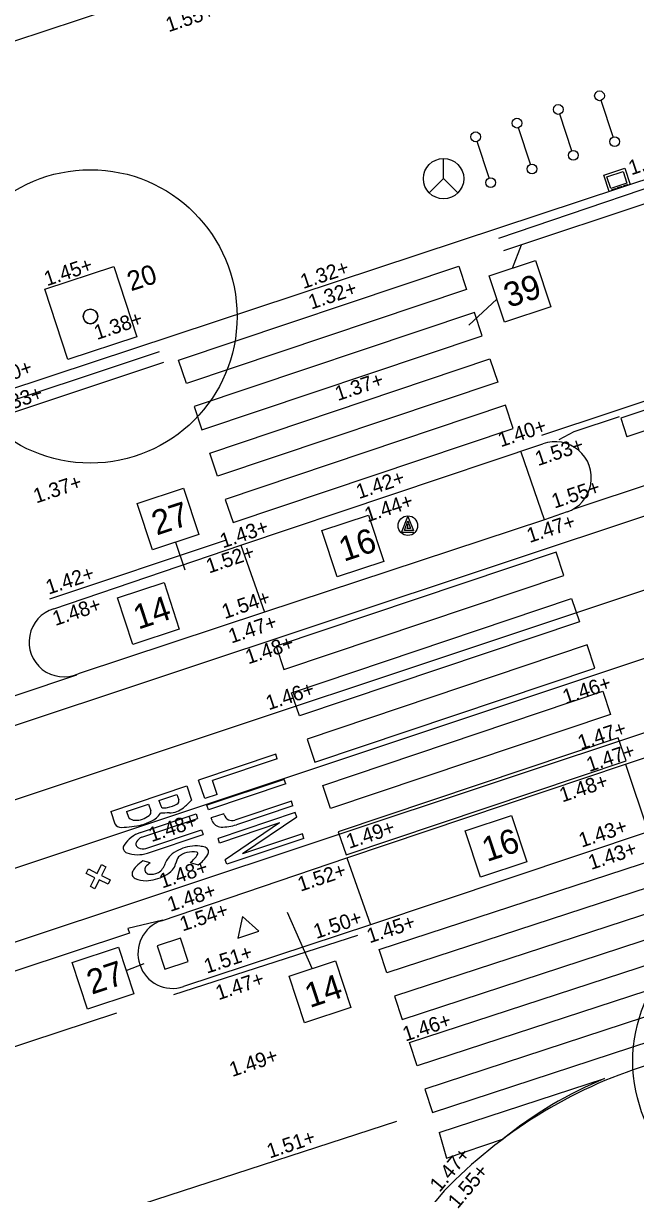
# Model space of a CAD drawing. Extents: x 122462 to 123306, y 485548 to 486417.
# Drawn here: x 122817.52 to 122830.05, y 486173.11 to 486197.04 of the extents above; entities that cross this region are included whole.
import ezdxf

# ---------------------------------------------------------------- set-up
doc = ezdxf.new("R2010")
doc.units = 0
for name, color, linetype in [('B meubilair trammast', 7, 'Continuous'), ('B-WE-GR-BOOM_BOOMDIAMETER', 7, 'Continuous'), ('B-WE-OG-HOOGTEPUNT-S', 7, 'Continuous'), ('B-WE-OG-TOPOKAART-G', 7, 'Continuous'), ('iba7-verkeersbord rood', 7, 'Continuous'), ('V markering 1-1 10 cm', 7, 'Continuous'), ('V markering figuratie', 7, 'Continuous'), ('V markering haaientanden', 7, 'Continuous'), ('V markering ononderbroken streep 10 cm', 7, 'Continuous'), ('V materiaalscheiding algemeen', 7, 'Continuous'), ('V meubilair ANWB paal', 7, 'Continuous'), ('V meubilair fietsenrek', 7, 'Continuous'), ('V meubilair verkeersbord', 7, 'Continuous'), ('V opsluitband 100x200 mm', 7, 'Continuous'), ('V Rails', 7, 'Continuous'), ('V riool trottoirkolk', 7, 'Continuous'), ('V Scheidingsband tramband', 7, 'Continuous'), ('V trottoirband 180-200x250 mm specie', 7, 'Continuous'), ('X-WE-AL-TEKENBLAD-S', 7, 'Continuous')]:
    doc.layers.add(name, color=color, linetype=linetype)

msp = doc.modelspace()

# ---------------------------------------------------------------- linework, layer by layer
at = {"layer": 'B meubilair trammast'}
msp.add_lwpolyline([(122821.912, 486178.335), (122822.339, 486178.475), (122822.004, 486178.776)], close=True, dxfattribs=at)
at = {"layer": 'B-WE-OG-TOPOKAART-G'}
msp.add_lwpolyline([(122815.999, 486196.239), (122819.975, 486197.551), (122824.066, 486198.901)], dxfattribs=at)
at = {"layer": 'iba7-verkeersbord rood'}
for centre, radius in [((122818.894, 486191.046), 3), ((122818.894, 486191.046), 0.15), ((122832.992, 486175.817), 3)]:
    msp.add_circle(centre, radius, dxfattribs=at)
for start, end in [(0, 180), (180, 0)]:
    msp.add_arc((122818.894, 486191.046), 0.15, start, end, dxfattribs=at)
at = {"layer": 'V markering 1-1 10 cm'}
for points in [[(122854.874, 486201.561), (122851.93, 486200.584), (122836.82, 486195.535), (122827.344, 486192.387)], [(122827.25, 486192.644), (122831.993, 486194.256)], [(122820.303, 486190.322), (122804.286, 486185), (122793.007, 486181.252)], [(122820.386, 486190.104), (122804.368, 486184.77), (122793.094, 486180.995)], [(122814.686, 486175.249), (122819.433, 486176.807)]]:
    msp.add_lwpolyline(points, dxfattribs=at)
at = {"layer": 'V markering figuratie'}
for p, q in [((122712.845, 486143.511), (122860.885, 486192.728)), ((122822.687, 486182.094), (122821.107, 486181.565)), ((122822.718, 486182), (122821.394, 486181.557)), ((122822.718, 486182), (122822.687, 486182.094)), ((122821.233, 486181.188), (122821.107, 486181.565)), ((122822.858, 486181.581), (122821.278, 486181.052)), ((122822.89, 486181.487), (122821.31, 486180.958)), ((122821.488, 486181.274), (122821.394, 486181.557)), ((122822.89, 486181.487), (122822.858, 486181.581)), ((122819.31, 486180.926), (122820.865, 486181.446)), ((122820.296, 486181.149), (122820.665, 486181.271)), ((122820.665, 486181.271), (122820.701, 486181.163)), ((122820.865, 486181.446), (122820.963, 486181.155)), ((122821.488, 486181.274), (122821.233, 486181.188)), ((122819.634, 486180.927), (122820.081, 486181.077)), ((122820.081, 486181.077), (122820.128, 486180.94)), ((122820.296, 486181.149), (122820.333, 486181.037)), ((122821.31, 486180.958), (122821.278, 486181.052)), ((122823.008, 486181.134), (122821.851, 486180.747)), ((122823.039, 486181.041), (122821.882, 486180.653)), ((122823.039, 486181.041), (122823.008, 486181.134)), ((122819.31, 486180.926), (122819.395, 486180.672)), ((122819.634, 486180.927), (122819.675, 486180.805)), ((122819.917, 486180.496), (122821.055, 486180.877)), ((122819.948, 486180.402), (122821.086, 486180.783)), ((122821.055, 486180.877), (122821.086, 486180.783)), ((122821.621, 486180.879), (122821.365, 486180.793)), ((122821.382, 486180.743), (122821.365, 486180.793)), ((122823.086, 486180.902), (122821.506, 486180.373)), ((122821.628, 486180.858), (122821.621, 486180.879)), ((122823.116, 486180.81), (122822.009, 486180.059)), ((122823.116, 486180.81), (122823.086, 486180.902)), ((122820.029, 486180.166), (122821.167, 486180.546)), ((122821.167, 486180.546), (122821.198, 486180.452)), ((122822.762, 486180.689), (122821.537, 486180.279)), ((122822.762, 486180.689), (122821.652, 486179.936)), ((122820.06, 486180.071), (122821.198, 486180.452)), ((122821.537, 486180.279), (122821.506, 486180.373)), ((122823.262, 486180.374), (122821.682, 486179.845)), ((122823.231, 486180.468), (122822.009, 486180.059)), ((122823.262, 486180.374), (122823.231, 486180.468)), ((122820.115, 486179.874), (122819.967, 486179.917)), ((122820.935, 486179.881), (122821.097, 486179.831)), ((122821.682, 486179.845), (122821.652, 486179.936))]:
    msp.add_line(p, q, dxfattribs=at)
for points in [[(122826.592, 486191.599), (122820.858, 486189.675), (122820.699, 486190.149), (122826.433, 486192.073)], [(122821.176, 486188.727), (122826.91, 486190.651), (122826.751, 486191.125), (122821.017, 486189.201)], [(122827.228, 486189.703), (122821.494, 486187.779), (122821.335, 486188.253), (122827.069, 486190.177)], [(122821.812, 486186.831), (122827.546, 486188.755), (122827.387, 486189.229), (122821.653, 486187.305)], [(122822.852, 486183.827), (122828.581, 486185.751), (122828.422, 486186.225), (122822.693, 486184.301)], [(122828.9, 486184.803), (122823.171, 486182.879), (122823.011, 486183.353), (122828.74, 486185.277)], [(122823.489, 486181.931), (122829.218, 486183.855), (122829.059, 486184.329), (122823.33, 486182.405)], [(122829.536, 486182.907), (122823.807, 486180.983), (122823.648, 486181.457), (122829.377, 486183.381)], [(122824.126, 486180.035), (122829.855, 486181.959), (122829.695, 486182.433), (122823.966, 486180.509)], [(122819.12, 486179.838), (122819.21, 486179.793), (122819.12, 486179.614), (122819.299, 486179.525), (122819.254, 486179.435), (122819.075, 486179.525), (122818.986, 486179.346), (122818.896, 486179.391), (122818.986, 486179.57), (122818.807, 486179.659), (122818.852, 486179.749), (122819.031, 486179.659)], [(122830.662, 486179.487), (122824.96, 486177.624), (122824.805, 486178.099), (122830.507, 486179.963)], [(122825.271, 486176.673), (122830.973, 486178.537), (122830.817, 486179.012), (122825.115, 486177.148)], [(122831.283, 486177.586), (122825.581, 486175.723), (122825.426, 486176.198), (122831.128, 486178.062)], [(122825.892, 486174.772), (122831.594, 486176.636), (122831.439, 486177.111), (122825.737, 486175.247)]]:
    msp.add_lwpolyline(points, close=True, dxfattribs=at)
for points in [[(122826.029, 486174.358), (122829.417, 486175.462)], [(122826.029, 486174.358), (122826.18, 486173.836), (122827.344, 486174.231)]]:
    msp.add_lwpolyline(points, dxfattribs=at)
for centre, radius, start, end in [((122820.398, 486181.057), 0.0675, 197.2524, 243.0662), ((122820.379, 486181.473), 0.476, 268.5689, 281.1936), ((122820.333, 486181.687), 0.695, 281.465, 298.5477), ((122820.49, 486181.387), 0.493, 272.2905, 308.6433), ((122820.635, 486181.14), 0.0697, 295.5776, 19.8117), ((122819.955, 486182.077), 1.366, 308.078, 317.5423), ((122819.699, 486180.814), 0.0256, 198.7735, 228.6878), ((122819.813, 486180.944), 0.199, 228.6878, 267.2153), ((122819.823, 486181.193), 0.448, 267.4989, 287.6099), ((122819.782, 486181.244), 0.51, 290.3181, 307.9776), ((122820.047, 486180.912), 0.0849, 304.6771, 18.905), ((122819.968, 486181.119), 0.428, 292.9181, 327.2918), ((122820.499, 486178.524), 2.37, 89.7455, 94.1316), ((122821.795, 486180.914), 0.176, 198.5084, 288.5084), ((122819.512, 486180.728), 0.13, 205.5478, 277.0875), ((122819.457, 486182.885), 2.287, 271.7957, 277.0839), ((122819.56, 486182.233), 1.628, 276.2971, 283.5646), ((122819.625, 486181.756), 1.15, 286.003, 296.2854), ((122821.572, 486180.807), 0.201, 198.5084, 268.4664), ((122821.591, 486181.522), 0.916, 268.4678, 288.5084), ((122820.158, 486179.841), 0.698, 110.1773, 145.4219), ((122819.905, 486180.256), 0.0816, 146.7834, 250.5599), ((122820.04, 486180.188), 0.233, 113.1225, 150.9839), ((122819.675, 486180.179), 0.109, 147.4911, 249.9891), ((122819.86, 486180.739), 0.698, 251.4584, 286.7029), ((122819.974, 486180.392), 0.233, 245.6159, 283.4773), ((122820.815, 486179.724), 0.413, 126.6151, 160.1416), ((122820.997, 486179.512), 0.692, 111.671, 128.1579), ((122820.925, 486179.762), 0.327, 99.9568, 134.4098), ((122821.099, 486179.242), 0.981, 99.9642, 111.426), ((122820.986, 486179.563), 0.534, 80.7646, 102.7272), ((122821.048, 486179.648), 0.573, 81.5189, 101.9729), ((122820.528, 486180.406), 0.666, 307.8236, 327.0926), ((122821.061, 486180.062), 0.0305, 326.6033, 70.3406), ((122821.071, 486179.637), 0.581, 72.5811, 83.8728), ((122821.213, 486180.098), 0.0987, 325.9572, 71.0302), ((122820.447, 486179.225), 0.842, 124.7705, 136.9964), ((122820.305, 486179.565), 0.362, 121.5479, 141.3153), ((122820.079, 486179.975), 0.365, 304.3033, 342.4534), ((122820.325, 486179.93), 0.322, 321.1525, 345.9772), ((122820.983, 486179.795), 0.35, 145.0731, 170.6952), ((122820.715, 486180.391), 0.678, 304.3623, 315.9404), ((122820.611, 486180.459), 0.8, 317.5739, 328.6429), ((122819.845, 486179.649), 0.101, 147.3653, 249.6796), ((122820.099, 486179.524), 0.384, 134.125, 151.991), ((122820.102, 486179.739), 0.0964, 146.7417, 255.9783), ((122820.142, 486179.946), 0.307, 258.1175, 297.6026), ((122819.964, 486180.477), 0.974, 285.6661, 297.1748), ((122820.123, 486180.196), 0.651, 296.0499, 314.0333), ((122820.043, 486180.102), 0.595, 246.9456, 268.9442), ((122819.992, 486180.352), 0.846, 272.7296, 286.1609), ((122832.526, 486167.865), 8.209, 112.2586, 129.1472)]:
    msp.add_arc(centre, radius, start, end, dxfattribs=at)
at = {"layer": 'V markering haaientanden'}
msp.add_lwpolyline([(122815.839, 486171.566), (122825.165, 486174.59)], dxfattribs=at)
at = {"layer": 'V markering ononderbroken streep 10 cm'}
for points in [[(122828.129, 486188.619), (122841.373, 486193.005), (122851.321, 486196.3)], [(122818.06, 486185.269), (122821.656, 486186.469)], [(122820.6, 486177.184), (122824.365, 486178.394)]]:
    msp.add_lwpolyline(points, dxfattribs=at)
at = {"layer": 'V materiaalscheiding algemeen'}
for points in [[(122828.771, 486187.102), (122837.36, 486189.952), (122848.716, 486193.729), (122856.341, 486196.233), (122866.652, 486199.655), (122878.268, 486203.536), (122881.909, 486204.772)], [(122828.488, 486188.532), (122828.792, 486188.691), (122829.724, 486188.997)], [(122802.962, 486178.476), (122818.617, 486183.717)], [(122820.373, 486178.699), (122819.656, 486178.534), (122819.692, 486178.438), (122804.62, 486173.448), (122804.792, 486172.968)]]:
    msp.add_lwpolyline(points, dxfattribs=at)
at = {"layer": 'V meubilair ANWB paal'}
for q in [(122826.121, 486194.276), (122825.829, 486193.571), (122826.413, 486193.571)]:
    msp.add_line((122826.121, 486193.863), q, dxfattribs=at)
msp.add_circle((122826.121, 486193.863), 0.413, dxfattribs=at)
at = {"layer": 'V meubilair fietsenrek'}
for p, q in [((122829.591, 486194.715), (122829.344, 486195.462)), ((122828.745, 486194.435), (122828.498, 486195.182)), ((122827.9, 486194.156), (122827.653, 486194.903)), ((122827.054, 486193.877), (122826.808, 486194.623))]:
    msp.add_line(p, q, dxfattribs=at)
for centre in [(122829.312, 486195.557), (122828.467, 486195.277), (122827.622, 486194.998), (122826.776, 486194.718), (122829.622, 486194.62), (122828.777, 486194.341), (122827.931, 486194.061), (122827.086, 486193.782)]:
    msp.add_circle(centre, 0.1, dxfattribs=at)
at = {"layer": 'V meubilair verkeersbord'}
msp.add_lwpolyline([(122825.515, 486186.63), (122825.263, 486186.63), (122825.39, 486186.953), (122825.504, 486186.668), (122825.319, 486186.668), (122825.39, 486186.868), (122825.446, 486186.708), (122825.377, 486186.708), (122825.39, 486186.748), (122825.391, 486186.798)], dxfattribs=at)
msp.add_lwpolyline([(122820.418, 486177.702), (122820.893, 486177.859), (122820.736, 486178.333), (122820.261, 486178.177)], close=True, dxfattribs=at)
msp.add_circle((122825.39, 486186.768), 0.2, dxfattribs=at)
at = {"layer": 'V opsluitband 100x200 mm'}
msp.add_lwpolyline([(122819.846, 486190.627), (122818.434, 486190.163), (122817.962, 486191.602), (122819.374, 486192.066)], close=True, dxfattribs=at)
at = {"layer": 'V Rails'}
for p, q in [((122714.919, 486148.627), (122859.557, 486196.72)), ((122715.373, 486147.26), (122860.011, 486195.354)), ((122712.39, 486144.878), (122860.43, 486194.095))]:
    msp.add_line(p, q, dxfattribs=at)
at = {"layer": 'V riool trottoirkolk'}
for p, q in [((122829.4, 486193.932), (122829.827, 486194.074)), ((122829.51, 486193.6), (122829.4, 486193.932)), ((122829.827, 486194.074), (122829.937, 486193.741)), ((122829.937, 486193.741), (122829.51, 486193.6)), ((122829.757, 486193.697), (122829.681, 486193.672)), ((122829.771, 486193.686), (122829.77, 486193.691)), ((122829.795, 486193.694), (122829.793, 486193.699)), ((122829.831, 486193.722), (122829.8, 486193.712)), ((122829.876, 486193.737), (122829.831, 486193.722)), ((122829.89, 486193.726), (122829.888, 486193.73)), ((122829.557, 486193.616), (122829.556, 486193.62)), ((122829.638, 486193.658), (122829.562, 486193.633)), ((122829.652, 486193.647), (122829.651, 486193.652)), ((122829.676, 486193.655), (122829.675, 486193.66))]:
    msp.add_line(p, q, dxfattribs=at)
msp.add_lwpolyline([(122829.463, 486193.901), (122829.796, 486194.01), (122829.874, 486193.773), (122829.542, 486193.663)], close=True, dxfattribs=at)
for centre, start, end in [((122829.76, 486193.688), 18.2994, 108.2994), ((122829.803, 486193.702), 108.2994, 198.2994), ((122829.879, 486193.727), 18.2994, 108.2994), ((122829.565, 486193.624), 108.2994, 198.2994), ((122829.641, 486193.649), 18.2994, 108.2994), ((122829.684, 486193.663), 108.2994, 198.2994)]:
    msp.add_arc(centre, 0.01, start, end, dxfattribs=at)
at = {"layer": 'V Scheidingsband tramband'}
msp.add_line((122829.745, 486188.966), (122829.871, 486188.586), dxfattribs=at)
for points in [[(122851.231, 486196.112), (122829.745, 486188.966)], [(122851.357, 486195.732), (122829.871, 486188.586)]]:
    msp.add_lwpolyline(points, dxfattribs=at)
at = {"layer": 'V trottoirband 180-200x250 mm specie'}
for points in [[(122829.844, 486181.895), (122838.722, 486184.858), (122839.696, 486185.175), (122850.112, 486188.608), (122857.676, 486191.147), (122870.119, 486195.296), (122871.261, 486195.673)], [(122833.081, 486194.781), (122818.107, 486189.829), (122805.552, 486185.683), (122794.641, 486182.031), (122786.085, 486179.205)], [(122855.472, 486188.85), (122851.096, 486187.401), (122844.912, 486185.348), (122841.457, 486184.188), (122835.7, 486182.292), (122830.306, 486180.508), (122824.624, 486178.607), (122820.8, 486177.343)], [(122818.143, 486185.068), (122821.969, 486186.367), (122828.151, 486188.439)], [(122828.184, 486186.889), (122827.708, 486188.271)], [(122828.649, 486187.048), (122828.184, 486186.889), (122822.459, 486184.996), (122818.64, 486183.741)], [(122821.969, 486186.367), (122822.459, 486184.996)], [(122820.349, 486178.691), (122824.142, 486179.974), (122829.844, 486181.895)], [(122829.844, 486181.895), (122830.306, 486180.508)], [(122824.142, 486179.974), (122824.624, 486178.607)]]:
    msp.add_lwpolyline(points, dxfattribs=at)
for centre, radius, start, end in [((122828.406, 486187.746), 0.739, 289.2084, 110.188), ((122818.348, 486184.388), 0.71, 106.7831, 294.2817), ((122820.577, 486178.018), 0.711, 108.6903, 288.2898), ((122833.26, 486166.297), 9.898, 107.4324, 136.042), ((122833.721, 486166.638), 10.009, 139.2783, 194.8273)]:
    msp.add_arc(centre, radius, start, end, dxfattribs=at)
at = {"layer": 'X-WE-AL-TEKENBLAD-S'}
for p, q in [((122827.53, 486192.033), (122827.714, 486192.509)), ((122827.212, 486191.402), (122826.635, 486190.87)), ((122820.638, 486186.431), (122820.824, 486185.866)), ((122823.434, 486177.711), (122822.927, 486178.858)), ((122819.627, 486177.673), (122819.993, 486177.814))]:
    msp.add_line(p, q, dxfattribs=at)
for points in [[(122827.055, 486191.877), (122828.005, 486192.19), (122828.318, 486191.24), (122827.369, 486190.927)], [(122819.849, 486187.224), (122820.799, 486187.537), (122821.112, 486186.587), (122820.163, 486186.274)], [(122823.632, 486186.67), (122824.582, 486186.983), (122824.895, 486186.033), (122823.946, 486185.72)], [(122819.45, 486185.291), (122820.4, 486185.604), (122820.713, 486184.654), (122819.764, 486184.341)], [(122826.56, 486180.531), (122827.51, 486180.844), (122827.823, 486179.895), (122826.874, 486179.581)], [(122818.521, 486177.835), (122819.471, 486178.148), (122819.784, 486177.198), (122818.834, 486176.885)], [(122822.959, 486177.554), (122823.909, 486177.868), (122824.222, 486176.918), (122823.272, 486176.605)]]:
    msp.add_lwpolyline(points, close=True, dxfattribs=at)

# ---------------------------------------------------------------- texts
at = {"layer": 'B-WE-GR-BOOM_BOOMDIAMETER'}
msp.add_text('20', height=0.4, rotation=18.3221, dxfattribs=at).set_placement((122819.724, 486191.557))
at = {"layer": 'B-WE-OG-HOOGTEPUNT-S'}
for s, rotation, p in [('1.55+', 18.2611, (122820.492, 486196.855)), ('1.39+', 18.3802, (122829.964, 486193.931)), ('1.45+', 18.3802, (122818.003, 486191.662)), ('1.32+', 18.3802, (122823.25, 486191.606)), ('1.32+', 18.3802, (122823.413, 486191.184)), ('1.38+', 18.3802, (122819.027, 486190.562)), ('1.40+', 18.5058, (122816.77, 486189.565)), ('1.37+', 18.3802, (122823.957, 486189.314)), ('1.33+', 18.4178, (122816.983, 486189.038)), ('1.40+', 18.3965, (122827.292, 486188.369)), ('1.53+', 18.3965, (122828.053, 486187.984)), ('1.37+', 18.4178, (122817.784, 486187.22)), ('1.42+', 18.3802, (122824.39, 486187.31)), ('1.55+', 18.3965, (122828.39, 486187.115)), ('1.44+', 18.3802, (122824.563, 486186.835)), ('1.43+', 18.6068, (122821.604, 486186.302)), ('1.47+', 18.3965, (122827.882, 486186.413)), ('1.52+', 18.6068, (122821.32, 486185.788)), ('1.42+', 18.3802, (122818.039, 486185.356)), ('1.54+', 18.6068, (122821.642, 486184.857)), ('1.48+', 18.3802, (122818.177, 486184.715)), ('1.47+', 18.6068, (122821.778, 486184.356)), ('1.48+', 18.6068, (122822.124, 486183.93)), ('1.46+', 18.343, (122828.615, 486183.114)), ('1.46+', 18.2967, (122822.542, 486182.991)), ('1.47+', 18.343, (122828.926, 486182.181)), ('1.47+', 18.343, (122829.103, 486181.729)), ('1.48+', 18.343, (122828.55, 486181.108)), ('1.48+', 18.3717, (122820.144, 486180.295)), ('1.49+', 18.343, (122824.188, 486180.16)), ('1.43+', 18.343, (122828.945, 486180.182)), ('1.43+', 18.343, (122829.14, 486179.728)), ('1.48+', 18.3717, (122820.362, 486179.348)), ('1.52+', 18.343, (122823.192, 486179.283)), ('1.48+', 18.3487, (122820.527, 486178.869)), ('1.54+', 18.3487, (122820.78, 486178.469)), ('1.50+', 18.343, (122823.517, 486178.316)), ('1.45+', 18.343, (122824.607, 486178.227)), ('1.51+', 18.3487, (122821.276, 486177.605)), ('1.47+', 18.3487, (122821.515, 486177.064)), ('1.46+', 18.2611, (122825.34, 486176.218)), ('1.49+', 18.343, (122821.796, 486175.493)), ('1.51+', 18.343, (122822.562, 486173.827)), ('1.47+', 50.0725, (122826.039, 486173.124)), ('1.55+', 50.0725, (122826.409, 486172.785))]:
    msp.add_text(s, height=0.3, rotation=rotation, dxfattribs=at).set_placement(p)
at = {"layer": 'X-WE-AL-TEKENBLAD-S'}
for s, p in [('39', (122827.454, 486191.218)), ('27', (122820.248, 486186.565)), ('16', (122824.079, 486186.027)), ('14', (122819.873, 486184.64)), ('16', (122827.007, 486179.889)), ('27', (122818.92, 486177.177)), ('14', (122823.382, 486176.904))]:
    msp.add_text(s, height=0.5, rotation=18.2603, dxfattribs=at).set_placement(p)

doc.saveas('drawing.dxf')
